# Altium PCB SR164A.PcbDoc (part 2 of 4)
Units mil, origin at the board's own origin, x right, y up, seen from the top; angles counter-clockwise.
Board outline 6100 x 4100 mil, 6 copper layers (Top Layer, Signal Layer 1, Signal Layer 2, Signal Layer 3, Signal Layer 4, Bottom Layer), stack 61.4 mil thick; 254 components, 116 nets, 656 pads, 2538 vias.
Unrouted connection lines stored in the file: 13.
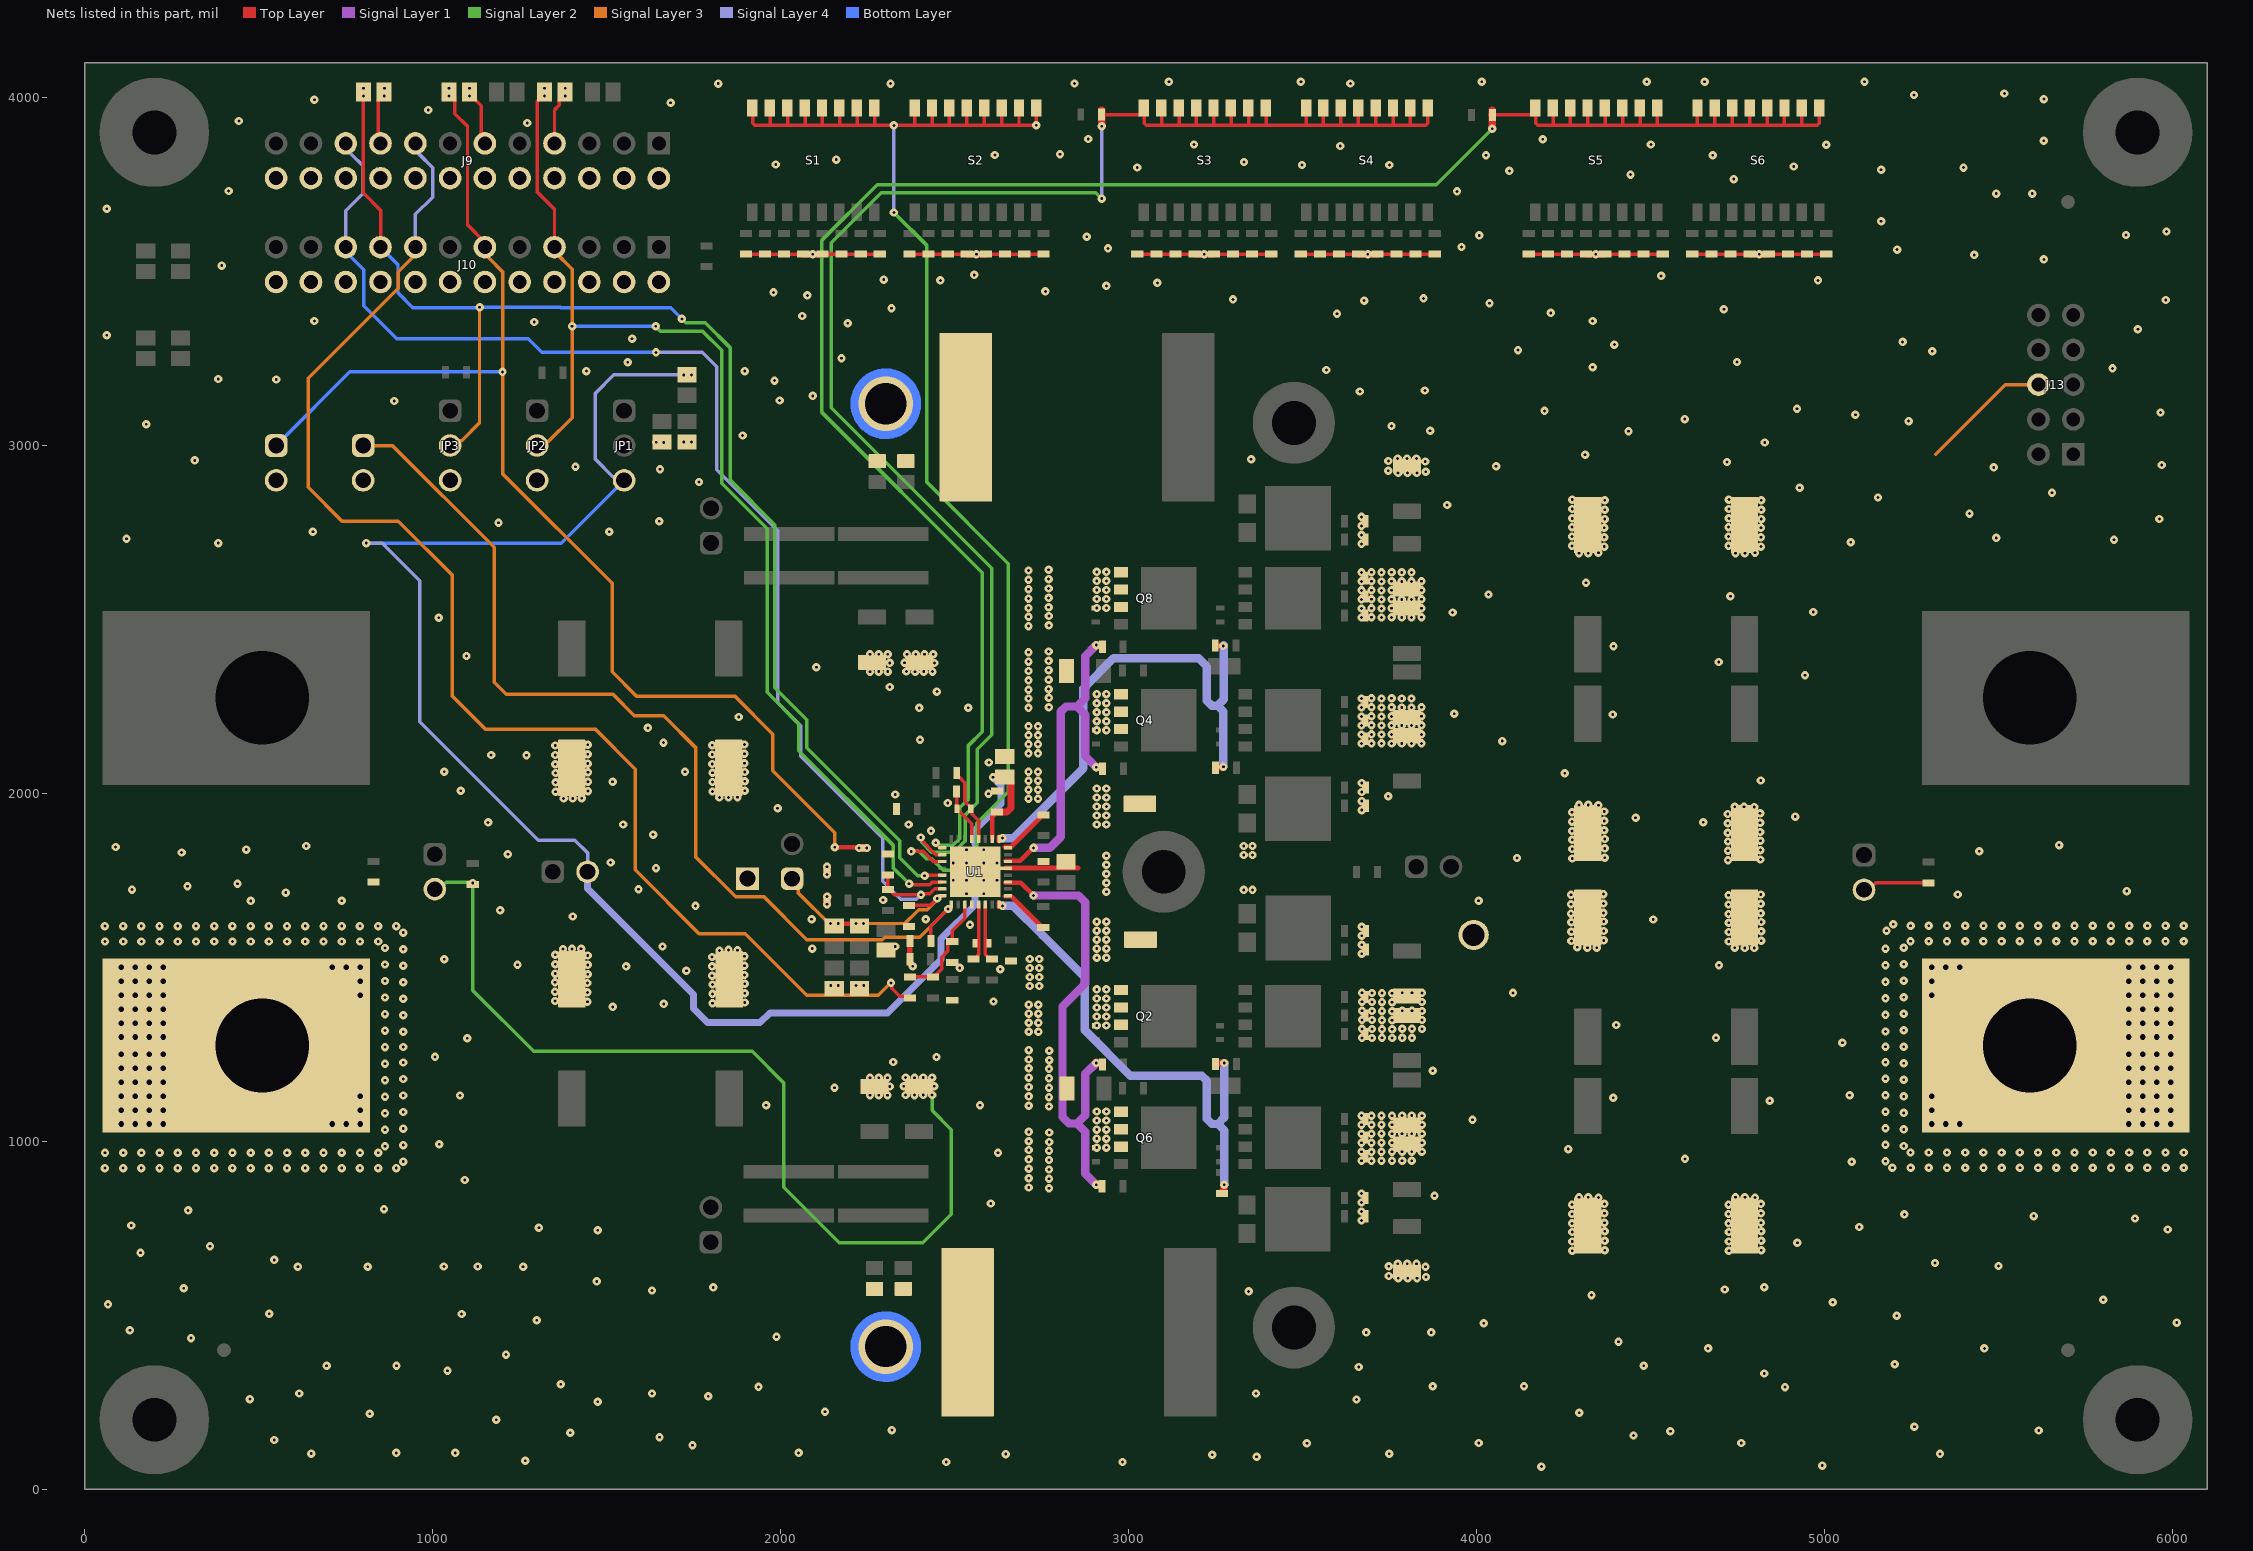
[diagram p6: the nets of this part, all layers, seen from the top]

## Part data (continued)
R47 R63 R79: library part CMP-0022509-4, "RES, 5.11 k, 1%, 0.1 W, AEC-Q200 Grade 0, 0603", Manufacturer=Vishay-Dale, Power_W=100mW, Supplier Part Number 1=541-5.11KHCT-ND, TempCo="100 ppm/C", Tolerance_%=1%, Value2=0.1W, Value_Code=5k11, ValueDisplayed=5.11k
R48 R64 R80: library part CMP-0022561-4, "RES, 6.49 k, 1%, 0.1 W, AEC-Q200 Grade 0, 0603", Manufacturer=Vishay-Dale, Power_W=100mW, Supplier Part Number 1=541-6.49KHCT-ND, TempCo="100 ppm/C", Tolerance_%=1%, Value2=0.1W, Value_Code=6k49, ValueDisplayed=6.49k
R49 R65 R81: library part CMP-0022635-4, "RES, 8.25 k, 1%, 0.1 W, AEC-Q200 Grade 0, 0603", Manufacturer=Vishay-Dale, Power_W=100mW, Supplier Part Number 1=541-8.25KHCT-ND, TempCo="100 ppm/C", Tolerance_%=1%, Value2=0.1W, Value_Code=8k25, ValueDisplayed=8.25k
R50 R66 R82: library part CMP-0022000-4, "RES, 10.5 k, 1%, 0.1 W, AEC-Q200 Grade 0, 0603", Manufacturer=Vishay-Dale, Power_W=100mW, Supplier Part Number 1=541-10.5KHCT-ND, TempCo="100 ppm/C", Tolerance_%=1%, Value2=0.1W, Value_Code=10k5, ValueDisplayed=10.5k
R51 R67 R83: library part CMP-0022043-4, "RES, 13.3 k, 1%, 0.1 W, AEC-Q200 Grade 0, 0603", Manufacturer=Vishay-Dale, Power_W=100mW, Supplier Part Number 1=541-13.3KHCT-ND, TempCo="100 ppm/C", Tolerance_%=1%, Value2=0.1W, Value_Code=13k3, ValueDisplayed=13.3k
R52 R68 R84: library part CMP-0022079-4, "RES, 16.2 k, 1%, 0.1 W, AEC-Q200 Grade 0, 0603", Manufacturer=Vishay-Dale, Power_W=100mW, Supplier Part Number 1=541-16.2KHCT-ND, TempCo="100 ppm/C", Tolerance_%=1%, Value2=0.1W, Value_Code=16k2, ValueDisplayed=16.2k
R53 R69 R85: library part CMP-0022205-4, "RES, 20.5 k, 1%, 0.1 W, AEC-Q200 Grade 0, 0603", Manufacturer=Vishay-Dale, Power_W=100mW, Supplier Part Number 1=541-20.5KHCT-ND, TempCo="100 ppm/C", Tolerance_%=1%, Value2=0.1W, Value_Code=20k5, ValueDisplayed=20.5k
R54 R70 R86: library part CMP-0022237-4, "RES, 24.9 k, 1%, 0.1 W, AEC-Q200 Grade 0, 0603", Manufacturer=Vishay-Dale, Power_W=100mW, Supplier Part Number 1=541-24.9KHCT-ND, TempCo="100 ppm/C", Tolerance_%=1%, Value2=0.1W, Value_Code=24k9, ValueDisplayed=24.9k
R55 R71 R87: library part CMP-0022324-4, "RES, 30.1 k, 1%, 0.1 W, AEC-Q200 Grade 0, 0603", Manufacturer=Vishay-Dale, Power_W=100mW, Supplier Part Number 1=541-30.1KHCT-ND, TempCo="100 ppm/C", Tolerance_%=1%, Value2=0.1W, Value_Code=30k1, ValueDisplayed=30.1k
R56 R72 R88: library part CMP-0022356-4, "RES, 36.5 k, 1%, 0.1 W, AEC-Q200 Grade 0, 0603", Manufacturer=Vishay-Dale, Power_W=100mW, Supplier Part Number 1=541-36.5KHCT-ND, TempCo="100 ppm/C", Tolerance_%=1%, Value2=0.1W, Value_Code=36k5, ValueDisplayed=36.5k
R89 R90 R103 R104: library part CMP-0022458-4, "RES, 4.99 k, 1%, 0.1 W, AEC-Q200 Grade 0, 0603", Manufacturer=Vishay-Dale, Power_W=100mW, Supplier Part Number 1=541-4.99KHCT-ND, TempCo="100 ppm/C", Tolerance_%=1%, Value2=0.1W, Value_Code=4k99, ValueDisplayed=4.99k
R91 R92 R96 R97 R98 R99 R100 R105 R106: library part CMP-0020442-3, "RES, 0, 5%, 0.125 W, AEC-Q200 Grade 0, 0805", Manufacturer=Vishay-Dale, Power_W=125mW, Supplier Part Number 1=541-0.0ACT-ND, TempCo="200 ppm/C", Tolerance_%=5%, Value2=0.125W, Value_Code=0000, ValueDisplayed=0
R93: library part CMP-0021246-3, "RES, 40.2 k, 1%, 0.125 W, AEC-Q200 Grade 0, 0805", Manufacturer=Vishay-Dale, Power_W=125mW, Supplier Part Number 1=541-40.2KCCT-ND, TempCo="100 ppm/C", Tolerance_%=1%, Value2=0.125W, Value_Code=40k2, ValueDisplayed=40.2k
R95: library part CMP-0025874-4, "RES, 0, 5%, 0.1 W, AEC-Q200 Grade 0, 0603", Manufacturer=Panasonic, Power_W=100mW, Supplier Part Number 1=P0.0GCT-ND, TempCo="600 ppm/C", Tolerance_%=5%, Value2=0.1W, Value_Code=0000, ValueDisplayed=0
R101 R102: library part CMP-0020842-3, "RES, 10.0 k, 1%, 0.125 W, AEC-Q200 Grade 0, 0805", Manufacturer=Vishay-Dale, Power_W=125mW, Supplier Part Number 1=541-10.0KCCT-ND, TempCo="100 ppm/C", Tolerance_%=1%, Value2=0.125W, Value_Code=10k0, ValueDisplayed=10.0k
S1 S2 S3 S4 S5 S6: library part CMP-0002229-1, "Switch, SPST, 8 Pos, 25mA, 24VDC, SMD", CurrentRating_mA=25A, Manufacturer="CTS Electrocomponents", Supplier Part Number 1=CT2188LPST-ND
SH-JP1 SH-JP2 SH-JP3 SH-JP4 SH-JP5 SH-JP6: library part CMP-0003642-1, "Shunt, 100mil, Flash Gold, Black", Manufacturer="Sullins Connector Solutions", Supplier Part Number 1=S9001-ND
T1 T2 T3 T4: library part CMP-0075010-2, "Terminal 70A Lug", Manufacturer=Panduit, Supplier Part Number 1=CXS70-14-C-ND
TP1 TP2 TP3 TP4: library part CMP-0067620-1, "PC Test Point, SMT", Manufacturer="TE Connectivity", Supplier Part Number 1=A106145CT-ND
TP5: library part CMP-0055143-2, "Test Point, Compact, Black, TH", Color=Black, Manufacturer="Keystone Electronics", Supplier Part Number 1=36-5006-ND
U1: library part CMP-0125346-2, "Wide-VIN, Dual-Phase, Automotive, Boost Controller With VOUT Tracking", Manufacturer="Texas Instruments", Max Supply Voltage=42V, Min Supply Voltage=2.5V, Operating Temperature Range="-40°C to +150°C", Output Voltage=6-60V, Switching Frequency=100-2200kHz
ZZ2: library part CMP-0077236-1
ZZ3: library part CMP-0077237-1
ZZ4: library part CMP-0077238-1
ZZ5 ZZ6 ZZ7 ZZ8 ZZ9 ZZ10: library part CMP-0077238-1, "These assemblies must comply with workmanship standards IPC-A-610 Class 2, unless otherwise specified."

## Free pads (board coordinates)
  round 236.22 hole 125.98: 2(3101,1775) 2(3475,465) 2(3475,3065)

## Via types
v1: diameter 24, hole 8, Top Layer to Bottom Layer, tented both sides, 2290 vias
v2: diameter 32, hole 16, Top Layer to Bottom Layer, 232 vias
v3: diameter 19.68, hole 7.87, Top Layer to Bottom Layer, tented both sides, 12 vias
v4: diameter 157.48, hole 118.11, Top Layer to Bottom Layer, tented both sides, 4 vias

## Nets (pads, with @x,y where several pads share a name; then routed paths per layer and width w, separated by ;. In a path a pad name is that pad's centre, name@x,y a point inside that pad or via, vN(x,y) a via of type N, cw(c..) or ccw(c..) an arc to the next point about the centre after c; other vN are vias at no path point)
AGND: C1.2 C2.1 C6.2 C7.2 C8.2 C15.2 C16.2 C17.2 C18.2 C19.2 C20.2 J7.2 J8.2 J9.2 J9.4 J9.6 J9.8 J9.10 J9.12 J9.14 J9.16 J9.18 J9.20 J9.22 J9.24 J10.2 J10.4 J10.6 J10.8 J10.10 J10.12 J10.14 J10.16 J10.18 J10.20 J10.22 J10.24 J13.6 J14.1 JP2.3 JP3.3 NT1.1 R5.1 R6.1 R7.1 R10.2 R41.2 R42.1 R43.2 R44.1 R45.2 R46.1 R47.1 R48.1 R49.1 R50.1 R51.1 R52.2 R53.1 R54.1 R55.1 R56.2 R57.2 R58.1 R59.2 R60.1 R61.2 R62.1 R63.1 R64.1 R65.1 R66.1 R67.1 R68.2 R69.1 R70.1 R71.1 R72.2 R73.2 R74.1 R75.2 R76.1 R77.2 R78.1 R79.1 R80.1 R81.1 R82.1 R83.1 R84.2 R85.1 R86.1 R87.1 R88.2 R91.1 R92.1 TP5.1 U1.4 U1.33 | length 2889
  Top Layer w10: C20.2@1635.96,3014.72 1646.48,3014.72 C20.2@1651.53,3009.67 ; R41.2@1900,3550 R42.1@1955,3550 R43.2@2010,3550 R44.1@2065,3550 ; R45.2@2120,3550 R46.1@2175,3550 R47.1@2230,3550 R48.1@2285,3550 ; R49.1@2370,3550 R50.1@2425,3550 R51.1@2480,3550 R52.2@2535,3550 ; C8.2@2371.16,1523.34 C8.2@2371.42,1523.6 ; C7.2@2371.42,1575.6 C7.2@2371.68,1575.86 ; R53.1@2590,3550 R54.1@2645,3550 R55.1@2700,3550 R56.2@2755,3550 ; R57.2@3025,3550 R58.1@3080,3550 R59.2@3135,3550 R60.1@3190,3550 ; R61.2@3245,3550 R62.1@3300,3550 R63.1@3355,3550 R64.1@3410,3550 ; R65.1@3495,3550 R66.1@3550,3550 R67.1@3605,3550 R68.2@3660,3550 ; R69.1@3715,3550 R70.1@3770,3550 R71.1@3825,3550 R72.2@3880,3550 ; R73.2@4150,3550 R74.1@4205,3550 R75.2@4260,3550 R76.1@4315,3550 ; R77.2@4370,3550 R78.1@4425,3550 R79.1@4480,3550 R80.1@4535,3550 ; R81.1@4620,3550 R82.1@4675,3550 R83.1@4730,3550 R84.2@4785,3550 ; R85.1@4840,3550 R86.1@4895,3550 R87.1@4950,3550 R88.2@5005,3550
  Top Layer w16: C8.2@2371.42,1523.6 C7.2@2371.42,1575.6
  Top Layer w19.5: R44.1@2065,3550 R45.2@2120,3550 ; R52.2@2535,3550 R53.1@2590,3550 ; R60.1@3190,3550 R61.2@3245,3550 ; R68.2@3660,3550 R69.1@3715,3550 ; R76.1@4315,3550 R77.2@4370,3550 ; R84.2@4785,3550 R85.1@4840,3550
  Top Layer w24: v1(1642.26,3009.19) C20.2@1664.06,3009.19 ; v1(1721.71,3010.08) R10.2@1743.51,3010.08 ; v1(2133.09,1767.29) C19.2@2133.09,1789.08 ; v1(2133.28,1681.63) C18.2@2133.28,1703.42 ; R92.1@2143.74,1442.26 R92.1@2165.53,1442.26 ; R91.1@2216.62,1442.26 R91.1@2238.41,1442.26
  Signal Layer 3 w10: 5320,2975 5520,3175 J13.6@5615,3175
  other v1: 4186.45,65.36 2475.91,78.74 2982.28,78.74 1266.1,81.95 3367.98,93.76 3748.98,102.35 895.32,104.67 4760.86,133.2 544.4,141.82 1651.67,149.42 4451.15,154.78 5258.39,180 1182.47,200 2127.4,222.78 1474.34,251.82 1791.88,267.68 616.14,275.59 3365.99,275.61 4886.58,293.85 4136.54,296.13 3661.65,351.69 895.67,355.06 4480.32,355.37 1210.63,387.3 305.12,434.65 1988.19,438.5 3869.81,451.15 129.68,457.09 6012.25,479.15 5208.03,499.02 529.9,504.41 4330.32,558.3 4713.32,574.26 1806.55,580.38 1471.4,597.62 1259.84,639.76 1031.98,640.62 5500.11,641.89 544.4,659.45 159.9,679.66 4922.23,708.9 5892.59,778.3 5229.67,790.26 296.86,801.8 859.84,805.43 3879.13,843.8 5078.44,941.3 1018.59,991.53 1958.21,1104.11 2573.06,1104.11 4842.86,1116.8 4393.2,1125.38 2154.58,1154.14 3874.24,1203.33 2323.29,1228.37 2448.08,1242.42 5051.46,1283.26 1098.92,1296.48 1517.58,1386.6 2611.67,1402.11 4104.99,1426.88 2143.74,1448.16 2165.7,1447.99 2216.62,1448.16 2238.58,1447.99 1729.06,1490.35 2630.99,1494.8 2514.73,1498.7 2379.78,1503.66 4696.64,1505.96 1243.43,1507.46 1032.9,1523.32 2090.75,1554.17 1660.51,1560 2329.61,1560.1 2544.08,1622.37 2088.91,1638.62 2416.76,1638.62 1755.3,1676.79 476.79,1691.26 2294.36,1693.93 2133.45,1703.59 5868.52,1719.34 135.59,1723.67 1591.34,1725 295.19,1733.52 2133.25,1789.25 1511.32,1801.79 4116.39,1814.44 1216.11,1825 464.1,1838.54 88.58,1846 636.21,1848.83 5674.44,1851.54 1633.34,1881.65 2432.24,1892.38 1547.19,1910.73 2367.74,1910.73 1159.12,1916.88 4457.26,1930.36 1991.29,1957.38 2480.18,1972.71 3746.27,1992.04 2329.59,1997.1 2597.23,1999.24 4817.01,2037.4 1032.9,2062.28 1725.03,2062.28 2598.54,2089.08 1269.35,2110.12 4073.61,2150.42 2400.55,2154.37 1618.38,2188.38 1879.57,2219.71 4391.5,2227.08 3935.85,2229.03 2539.3,2246.05 2449.02,2292.72 2313.73,2305.79 4943.91,2340 2102.77,2362.94 1097.22,2395.24 1017.3,2505.09 3931.27,2520.26 4729.64,2566.76 4314.5,2605.44 383.49,2719.54 5075.71,2722.3 5832.3,2729.02 119.73,2732 655.59,2751.99 1651.03,2782.43 5416.82,2804.32 3915.4,2828.93 1653.2,2931.91 1410.41,2939.01 5969.45,2944.16 316.11,2957.29 4311.97,2973.74 1664.22,3009.03 4828.3,3008.7 1743.67,3009.91 1890.63,3028.67 3866.49,3042.32 176.53,3060.84 4598.16,3075.85 5088.82,3088.3 889.59,3127.82 2092.5,3142.71 3664.79,3155.26 1982.08,3186.63 550,3189.56 383.49,3191.15 1441.62,3213.93 1896.93,3213.93 1560.43,3239.5 2174.67,3250.7 4396.27,3290.09 5224.54,3297.79 1573.09,3307.09 62.95,3316.93 5900.88,3334.1 2193,3351.42 1291.78,3355.15 659.93,3357.93 3598.91,3378.47 4213.39,3381.16 4710.9,3391.92 3847.66,3422.84 2076.77,3431.44 2936.25,3458.82 2458.99,3474.68 393.7,3517.18 5430.27,3547.89 2092.5,3550 2562.5,3550 3217.5,3550 3687.5,3550 4342.5,3550 4812.5,3550 2879.54,3600.33 4007.65,3603.97 5982.9,3615.12 5162.69,3644.7 62.95,3680.5 5597,3724.03 3944.05,3730.31 413.39,3731.41 4739.14,3765.72 4442.47,3778.63 3025,3799.21 5399.5,3798.74 1985.87,3807.67 3331.78,3814.85 4027.05,3834.1 2615.69,3834.79 3608.07,3861.07 5005,3864.15 4190.54,3880.01 2883.86,3880.89 1271.79,3926.76 442.91,3932.74 987.11,3964.36 1683.75,3985.27 659.93,3994.06 5630.61,3995.64 3637.39,4040.57 3115.77,4045.28 4655.51,4045.28 5115.17,4045.28
  other v3: 2534.2,1712.01 2583.8,1712.01 2496.01,1750.2 2534.2,1750.2 2583.8,1750.2 2621.99,1750.2 2496.01,1799.8 2534.2,1799.8 2583.8,1799.8 2621.99,1799.8 2534.2,1837.99 2583.8,1837.99
ATRK/DTRK: C17.1 JP5.1 R93.2 R94.2 U1.32 | length 698.8
  Top Layer w10: C17.1@2369.19,1672.83 C17.1@2369.19,1678.24 ; C17.1@2385.28,1678.24 2430.1,1678.24 v1(2449.92,1698.07) v1@2449.92,1698.25 ; U1.32@2457.78,1706.1 U1.32@2464.51,1706.1
  Top Layer w12: R94.2@2165.17,1625.32 R93.2@2216.69,1625.32
  Top Layer w16: v1@2449.81,1697.29 U1.32@2455.47,1702.94
  Top Layer w24: v1(2143.57,1626.39) R94.2@2165.36,1626.39 ; v1(2216.45,1626.39) R93.2@2238.25,1626.39
  Signal Layer 3 w10: JP5.1@2032.92,1754.76 2049.95,1737.73 2049.95,1715.14 v1@2143.74,1621.35 ; v1@2150.52,1623.86 v1@2165.53,1623.86 ; v1(2165.53,1626.23) v1@2216.29,1626.23 ; v1@2216.62,1621.79 2217.14,1621.27 2238.06,1621.27 v1@2238.58,1621.79 ; v1(2238.41,1626.23) 2356.44,1626.23 2392.15,1661.94 2396.31,1666.1 2421.06,1666.1 2449.92,1694.97 v1(2449.92,1698.07)
ATRK_EXT: J8.1 J10.11 R99.1 R104.2 | length 3640.4
  Top Layer w10: R99.1@1046.87,4015.75 1063.52,3999.09 1063.52,3953.49 1099.92,3917.09 1099.92,3633.99 1150,3583.91 J10.11@1150,3570
  Top Layer w12: v1(2155.21,1845.18) R104.2@2244.29,1845.18 ; R104.2@2234.6,1845.18 R104.2@2236.35,1843.43
  Top Layer w24: v1(2225.46,1843.43) R104.2@2247.25,1843.43
  Signal Layer 3 w10: J10.11@1160.52,3559.48 1160.52,3539.78 1200.6,3499.7 v1(1200.6,3211.56) 1200.6,2919.05 1515.62,2604.03 1515.62,2349.38 1585,2280 1867.8,2280 1977.16,2170.64 1977.16,2065.07 2155.21,1887.02 v1(2155.21,1845.18)
  Signal Layer 4 w10: J10.11@1150,3570 J10.11@1160.52,3559.48
  Bottom Layer w10: J8.1@551.18,3012.89 562.89,3012.89 761.56,3211.56 v1(1200.6,3211.56)
  other v1: 2247.42,1843.26 1046.7,4004.68 1046.87,4026.64
ATRK_EXT_SEC: J9.11 R99.2 | length 165.7
  Top Layer w10: R99.2@1105.92,4015.75 1105.92,4009.84 1139.01,3976.76 1139.01,3901.65 1139.48,3901.18 1139.48,3878.83 J9.11@1150,3868.31
  other v1: 1105.76,4004.68 1105.92,4026.64
BIAS: C1.1 C2.2 JP1.3 JP4.2 R9.1 U1.18 | length 4888.6
  Top Layer w10: C2.2@2644.11,2046.9 C2.2@2644.25,2046.77
  Top Layer w13: U1.18@2608.21,1869.49 2608.21,1932.5 C1.1@2615.83,1940.11
  Top Layer w20: C1.1@2621.99,1947.06 2650.14,1947.06 2661.85,1958.78 2661.85,2035.07 2650.15,2046.77 C2.2@2644.25,2046.77
  Top Layer w22: v1@2611.01,2046.9 C2.2@2644.11,2046.9
  Top Layer w24: v1(1721.71,3202.98) R9.1@1743.51,3202.98
  Signal Layer 4 w10: v1(808.96,2719.54) 854.5,2719.54 963.13,2610.91 963.13,2206.35 1303.6,1865.88 1408.15,1865.88 1445,1829.03 JP4.2@1445,1775 ; JP1.3@1539.48,2910.52 1517.85,2910.52 1467.76,2960.61 1467.76,3150.57 1520.16,3202.98 v1(1721.71,3202.98)
  Signal Layer 4 w14: 2559,1698.29 2559,1858.29
  Signal Layer 4 w20: JP4.2@1445,1775 1445,1726.52 1749.93,1421.59 1749.93,1381.6 1790.27,1341.26 1941.2,1341.26 1969.19,1369.25 2307.32,1369.25 2461.28,1523.21 2461.28,1582.45 2558.83,1680.01 2558.83,1699.23 ; 2558.33,1855.19 2558.33,1894.93 2633.28,1969.88 2633.28,2001.6 2633.28,2023.56 v1(2610.25,2046.6)
  Bottom Layer w10: v1(808.96,2719.54) 1369.54,2719.54 JP1.3@1550,2900 JP1.3@1539.48,2910.52
  other v1: 1743.67,3202.81
CFG0: S1.9 S1.10 S1.11 S1.12 S1.13 S1.14 S1.15 S1.16 S2.9 S2.10 S2.11 S2.12 S2.13 S2.14 S2.15 S2.16 U1.27 | length 4212.1
  Top Layer w10: S1.16@1920,3970 1920,3925.86 1925.86,3920 1970,3920 ; S1.15@1970,3970 1970,3920 ; S1.14@2020,3970 2020,3920 ; 2070,3921 S1.13@2070,3970.79 ; 2120,3920 2020,3920 ; 2120,3920.79 S1.12@2120,3970.79 ; 2121,3920 2169,3920 ; S1.11@2170,3970.79 2170,3920 v1(2325.46,3920) 2729.14,3920 2735,3925.86 S2.9@2735,3970 ; 2220,3921 S1.10@2220,3970.79 ; 2270,3920.79 S1.9@2270,3970.79 ; v1@2377.23,1833.44 2377.38,1833.59 2409.89,1833.59 2439.1,1804.39 2455.75,1804.39 2455.81,1804.45 U1.27@2457.7,1804.45 ; 2385,3920.79 S2.16@2385,3970 S2.16@2385,3970.79 ; 2435,3920.79 S2.15@2435,3970 S2.15@2435,3970.79 ; 2485,3921.79 S2.14@2485,3970 S2.14@2485,3971.57 ; 2535,3921.57 S2.13@2535,3970 S2.13@2535,3971.57 ; 2585,3920.79 S2.12@2585,3970 S2.12@2585,3971.57 ; 2635,3921.79 S2.11@2635,3970 S2.11@2635,3971.57 ; 2685,3921.57 S2.10@2685,3970 S2.10@2685,3971.57 ; 1970,3920 2020,3920
  Signal Layer 2 w10: v1(2325.46,3669.74) 2420.46,3574.74 2420.46,2894.45 2654.44,2660.47 2654.44,2004.84 2562.96,1913.36 2562.96,1797.42 2544.5,1778.96 2467.19,1778.96 2433.64,1812.51 2418.29,1812.51 2397.21,1833.59 2392.15,1833.59 v1@2377.38,1833.59
  Signal Layer 4 w10: v1(2325.46,3669.74) v1(2325.46,3920)
  other v1: 2375.4,1833.44 2734.46,3920.25
CFG1: R39.2 S3.9 S3.10 S3.11 S3.12 S3.13 S3.14 S3.15 S3.16 S4.9 S4.10 S4.11 S4.12 S4.13 S4.14 S4.15 S4.16 U1.26 | length 4996
  Top Layer w10: v1@2403.61,1866.64 2446.04,1824.21 U1.26@2457.7,1824.21 ; R39.2@2928,3950.31 S3.16@3043.9,3950.31 ; S3.16@3045,3970 3045,3925.86 3050.86,3920 3245,3920 3854.14,3920 3860,3925.86 S4.9@3860,3970 ; 3095,3920.79 S3.15@3095,3970.79 ; 3145,3920.79 S3.14@3145,3970.79 ; 3195,3921.79 S3.13@3195,3971.57 ; 3245,3921.57 S3.12@3245,3971.57 ; 3295,3920.79 S3.11@3295,3971.57 ; 3345,3921.79 S3.10@3345,3971.57 ; 3395,3921.57 S3.9@3395,3971.57 ; 3510,3920.79 S4.16@3510,3970 S4.16@3510,3970.79 ; 3560,3920.79 S4.15@3560,3970 S4.15@3560,3970.79 ; 3610,3921.79 S4.14@3610,3970 S4.14@3610,3971.57 ; 3660,3921.57 S4.13@3660,3970 S4.13@3660,3971.57 ; 3710,3920.79 S4.12@3710,3970 S4.12@3710,3971.57 ; 3760,3921.79 S4.11@3760,3970 S4.11@3760,3971.57 ; 3810,3921.57 S4.10@3810,3970 S4.10@3810,3971.57
  Top Layer w22: R39.2@2922.44,3951.1 2922.62,3950.93 2922.62,3917.56 v1(2922.79,3917.39) ; R39.2@2922.62,3951.28 R39.2@2922.62,3963.43
  Signal Layer 2 w10: v1@2404.27,1869.49 2405.37,1868.39 2405.37,1859.3 2432.99,1831.67 2498.4,1831.67 2530.27,1863.54 2530.27,1938.03 2565.01,1972.76 2565.01,2001.6 2565.01,2127.28 2606.9,2169.17 2606.9,2647.66 2145.67,3108.89 2145.67,3582.77 2289.38,3726.48 2905.97,3726.48 v1(2922.79,3709.66)
  Signal Layer 4 w10: v1(2922.79,3709.66) v1(2922.79,3917.39)
  other v1: 2402.69,1873.39
CFG2: R40.2 S5.9 S5.10 S5.11 S5.12 S5.13 S5.14 S5.15 S5.16 S6.9 S6.10 S6.11 S6.12 S6.13 S6.14 S6.15 S6.16 U1.25 | length 5889.6
  Top Layer w10: v1@2446.44,1859.14 2449.12,1856.46 2449.12,1852.55 2457.78,1843.9 U1.25@2464.51,1843.9 ; R40.2@4045.28,3950.31 S5.16@4168.9,3950.31 ; S5.16@4170,3970 4170,3950.31 4170,3925.86 4175.86,3920 4220,3920 4270,3920 4320,3920 4370,3920 4420,3920 4470,3920 4520,3920 4577.5,3920 4635,3920 4685,3920 4735,3920 4785,3920 4835,3920 4885,3920 4935,3920 4979.14,3920 4985,3925.86 S6.9@4985,3970 ; 4220,3920.79 S5.15@4220,3970.79 ; 4270,3920.79 S5.14@4270,3970.79 ; 4320,3921.79 S5.13@4320,3971.57 ; 4370,3921.57 S5.12@4370,3971.57 ; 4420,3920.79 S5.11@4420,3971.57 ; 4470,3921.79 S5.10@4470,3971.57 ; 4520,3921.57 S5.9@4520,3971.57 ; 4635,3920.79 S6.16@4635,3970 S6.16@4635,3970.79 ; 4685,3920.79 S6.15@4685,3970 S6.15@4685,3970.79 ; 4735,3921.79 S6.14@4735,3970 S6.14@4735,3971.57 ; 4785,3921.57 S6.13@4785,3970 S6.13@4785,3971.57 ; 4835,3920.79 S6.12@4835,3970 S6.12@4835,3971.57 ; 4885,3921.79 S6.11@4885,3970 S6.11@4885,3971.57 ; 4935,3921.57 S6.10@4935,3970 S6.10@4935,3971.57
  Top Layer w22: R40.2@4044.61,3950.31 4044.89,3950.03 v1(4044.89,3910.3) ; R40.2@4045.28,3950.31 R40.2@4045.3,3963.38
  Signal Layer 2 w10: v1@2446.44,1859.14 2448.49,1859.14 2456.86,1850.77 2494.87,1850.77 2514.27,1870.17 2514.27,1958.72 2539.72,1984.17 2539.72,2001.6 2539.72,2137.97 2579.47,2177.71 2579.47,2634.4 2117.41,3096.46 2117.41,3589.24 2278,3749.83 3884.42,3749.83 v1(4044.89,3910.3)
  other v1: 2445.47,1858.37
COMP: J9.15 J10.15 R95.1 | length 3912.3
  Top Layer w10: v1@2316.48,1463.18 2319.16,1460.5 2319.16,1439.94 2341.69,1417.4 2366.77,1417.4 R95.1@2371.77,1412.4
  Signal Layer 3 w10: J10.15@939.48,3559.48 939.48,3537.85 900.65,3499.02 900.65,3452.33 641.98,3193.66 641.98,2879.78 739.32,2782.43 901.15,2782.43 1056.75,2626.83 1056.75,2279.12 1151.9,2183.97 1468.01,2183.97 1581.98,2070 1581.98,1780.35 1765.35,1596.98 1897.91,1596.98 2074.5,1420.4 2280.95,1420.4 v1@2316.12,1455.57
  Signal Layer 4 w10: J10.15@939.48,3559.48 J10.15@950,3570 950,3664.15 999.85,3714 999.85,3798.52 960.52,3837.86 960.52,3857.79 J9.15@950,3868.31
  other v1: 2317.23,1455.54
CSN1: C11.2 R16.1 U1.5 | length 172.1
  Top Layer w10: R16.1@2554.63,1524.14 2568.84,1538.35 2568.84,1592.6 U1.5@2568.84,1680.51 ; C11.2@2558.41,1569.32 2568.3,1569.32
CSN2: C12.1 R18.1 U1.21 | length 154.2
  Top Layer w10: R18.1@2505.92,2005.78 2505.92,2001.6 2505.92,1955.83 2549.16,1912.59 U1.21@2549.16,1869.49
CSP1: C11.1 R15.1 U1.6 | length 182.4
  Top Layer w10: U1.6@2588.53,1680.51 2588.53,1592.6 2588.53,1569.32 ; C11.1@2595.91,1576.32 C11.1@2598.41,1573.82 ; C11.1@2598.41,1569.32 2588.53,1569.32 ; R15.1@2607.39,1522.98 2601.26,1522.98 2595.1,1529.14 2595.1,1530.56 2588.53,1537.13 2588.53,1569.32
CSP2: C12.2 R17.1 U1.20 | length 217.8
  Top Layer w10: R17.1@2506.08,2059.06 2506.08,2051.56 2511.08,2046.56 2513.88,2046.56 2529.47,2030.97 2529.47,2001.6 2529.47,1977.18 2543.14,1963.52 2544.08,1963.52 2546.58,1961.02 C12.2@2546.58,1956.52 2549.08,1954.02 2549.08,1941.17 2568.87,1921.38 U1.20@2568.87,1869.52
DLY: C7.1 J7.1 U1.1 | length 2840.8
  Top Layer w10: C7.1@2431.68,1575.86 2431.68,1592.6 2431.68,1618.55 v1(2481.22,1668.09) 2484.41,1668.09 U1.1@2490.02,1673.7
  Signal Layer 3 w10: J7.1@800,3000 883.79,3000 1176.72,2707.08 1176.72,2319.36 1211.08,2285 1518.14,2285 1579.63,2223.51 1664.03,2223.51 1755.3,2132.24 1755.3,1818.43 1870.56,1703.17 1952.14,1703.17 2075.37,1579.93 2292.42,1579.93 2299.43,1586.94 2400.07,1586.94 2405.73,1592.6 v1(2481.22,1668.09)
EN2: J10.7 JP2.2 R97.1 U1.30 | length 3463.1
  Top Layer w10: v1(1320.96,4004.73) 1316.11,4004.73 1299.74,3988.37 1299.74,3728.98 1350,3678.73 J10.7@1350,3570 ; v1(2369.19,1740.55) 2371.77,1737.97 2428.93,1737.97 2436.35,1745.39 2464.43,1745.39 U1.30@2464.51,1745.47
  Top Layer w24: R97.1@1321.13,4004.9 v1(1321.13,4026.69)
  Signal Layer 2 w10: v1(1640.82,3342.69) 1654.44,3329.06 1774.65,3329.06 1830.35,3273.36 1830.35,2891.75 1960.92,2761.18 1960.92,2291.33 2052.52,2199.74 2052.52,2122.22 2322.98,1851.76 2322.98,1786.76 v1(2369.19,1740.55)
  Signal Layer 3 w10: JP2.2@1305.84,3002.28 1314.07,3010.52 1331.22,3010.52 1400.53,3079.83 v1(1400.53,3342.69) 1400.95,3343.11 1400.95,3506.6 1350,3557.55 J10.7@1350,3570
  Bottom Layer w10: v1(1400.53,3342.69) v1(1640.82,3342.69)
  Bottom Layer w24: v1@1321.13,4004.9 v1(1321.13,4026.69)
EN2_SEC: J9.7 R97.2 | length 195.9
  Top Layer w10: J9.7@1350,3868.31 1350,3964.36 1364.13,3978.49 1364.13,3993.19 1375.67,4004.73 v1(1380.96,4004.73)
  Top Layer w24: R97.2@1381.13,4004.9 v1(1381.13,4026.69)
  Bottom Layer w24: v1@1381.13,4004.9 v1(1381.13,4026.69)
GND: C3.2 C4.2 C21.1 C22.1 C23.1 C24.1 C25.1 C26.1 C27.1 C28.1 C29.2 C30.2 C31.1 C32.1 C33.1 C34.1 C35.1 C36.1 C37.1 C38.1 C39.1 C40.1 C41.2 C42.2 C43.2 C44.2 C45.2 C46.2 C47.2 C48.2 C49.2 C50.2 C51.2 C52.2 C53.2 C54.2 C55.2 C56.2 C57.2 C58.2 C59.2 C60.2 C61.1 C62.1 C63.1 C64.1 C65.1 C66.1 C67.1 C68.1 C69.2 J2.1 J4.1 J5.2 J6.2 NT1.2 Q2.1 Q2.2 Q2.3 Q4.1 Q4.2 Q4.3 Q6.1 Q6.2 Q6.3 Q8.1 Q8.2 Q8.3 R29.1 R30.1 R32.1 R34.1 R36.1 R38.1 T2.1 T4.1 TP3.1 TP4.1 U1.13 | length 3126.2
  Top Layer w10: J6.2@5113.01,1726.89 5128.44,1726.89 5132.18,1726.89 5128.44,1723.15 J6.2@5113.57,1723.15 5127.21,1723.15 5131.56,1727.5 5146.9,1742.85 C69.2@5299.21,1742.85
  Top Layer w13.5: U1.13@2646.2,1785.95 2685.2,1785.95
  Top Layer w15: 2683.79,1785.88 2819.75,1785.88 2853.79,1785.88
  Signal Layer 2 w10: J5.2@1020.27,1727 1021.11,1727 1039.32,1745.2 1115.22,1745.2 1115.22,1433.76 1290.33,1258.65 1918.12,1258.65 2008.86,1167.9 2008.86,868.03 2168.51,708.38 2408.24,708.38 2490.81,790.96 2490.81,1033.28 2435.2,1088.9 v1(2435.2,1133.31)
  Signal Layer 4 w10: J5.2@991.18,1715.06 1004.45,1715.06 J5.2@1004.45,1717.06 ; v1@2409.71,1139.47 v1@2412.23,1136.94
  other v1: 4993.69,68.11 3240.45,99.46 2647.07,101.17 5332.12,101.91 650.99,102.65 1064.69,104.67 2051.49,104.67 1746.77,126.87 3512.33,132.35 4006.14,133.2 1395.15,162.75 4557.22,166.89 5616.08,169.29 2319.63,170.14 818.97,217.47 4294.91,219.83 3654.79,258.33 474.55,259.32 1630.13,275.59 1936.47,294.36 3874.27,296.13 1368.11,301.97 4826.76,332.93 1042.49,340.78 694.95,355.06 5202.17,359.4 4665.51,405.13 5459.66,405.13 4408.02,424.38 3682.79,451.15 4020.58,477.32 1298.77,486.07 1082.92,503.95 66.84,531.5 5024.09,537.48 5801.38,544.7 3345,568.98 1630.13,571.55 284.63,577.99 4826.74,580.8 3775.04,606.78 3802.04,606.78 3829.04,606.78 3854.76,610.46 3747.88,613.27 612.5,639.76 813.52,639.76 3853.29,639.73 1129.4,640.62 3747.88,640.9 3773.59,648.14 3800.59,648.14 3827.59,648.14 5317.68,650.59 4275.29,685.41 4725.25,685.41 4368.33,687.45 4818.29,687.45 359.87,698.82 4275.29,712.41 4725.25,712.41 4368.33,714.45 4818.29,714.45 4275.29,739.41 4725.25,739.41 4368.33,741.45 4818.29,741.45 1474.34,744.38 5986.68,746.85 1305.02,751.81 5099.81,754.07 133.34,758.25 4274.33,764.41 4724.29,764.41 4367.37,766.45 4817.33,766.45 3669.26,772.48 5601.64,785.35 4274.33,791.41 4724.29,791.41 4367.37,793.45 4817.33,793.45 3669.26,798.41 4274.33,818.41 4724.29,818.41 4367.37,820.45 4817.33,820.45 2604.04,821.51 3669.26,824.34 4350.33,838.37 4800.29,838.37 4294.33,839.37 4321.33,839.37 4744.29,839.37 4771.29,839.37 3669.26,850.26 2771.13,865.36 2713.22,867.36 1092.23,888.92 2771.13,892.36 2713.22,894.36 2771.13,919.36 2713.22,921.36 57.72,923.14 110.07,923.14 162.42,923.14 214.77,923.14 267.12,923.14 319.47,923.14 371.82,923.14 424.17,923.14 476.52,923.14 528.87,923.14 581.22,923.14 633.57,923.14 685.92,923.14 738.27,923.14 790.62,923.14 842.97,923.14 895.32,923.14 5195.28,924.06 5247.63,924.06 5299.98,924.06 5352.33,924.06 5404.68,924.06 5457.03,924.06 5509.38,924.06 5561.73,924.06 5614.08,924.06 5666.43,924.06 5718.78,924.06 5771.13,924.06 5823.48,924.06 5875.83,924.06 5928.18,924.06 5980.53,924.06 6032.88,924.06 915,941.86 5175.6,942.78 3669.26,944.43 3698.14,944 3756.91,944.14 3727.02,944.57 3786.09,944.51 3814,944.51 2771.13,946.36 2713.22,948.36 4599.06,949.76 57.99,967.3 110.34,967.3 162.69,967.3 215.04,967.3 267.39,967.3 319.74,967.3 372.09,967.3 424.44,967.3 476.79,967.3 529.14,967.3 581.49,967.3 633.84,967.3 686.19,967.3 738.54,967.3 790.89,967.3 843.24,967.3 2624.77,967.07 5247.36,968.23 5299.71,968.23 5352.06,968.23 5404.41,968.23 5456.76,968.23 5509.11,968.23 5561.46,968.23 5613.81,968.23 5666.16,968.23 5718.51,968.23 5770.86,968.23 5823.21,968.23 5875.56,968.23 5927.91,968.23 5980.26,968.23 6032.61,968.23 3669.26,970.36 3698.14,969.93 3727.02,970.5 3756.91,970.07 3786.09,970.44 3814,970.44 3842.89,970.01 2771.13,973.36 2713.22,975.36 4263.33,977.77 2908.75,982.08 2936.25,982.08 862.92,986.02 5227.68,986.95 915,989.34 5175.6,990.27 3669.26,996.28 3698.14,995.85 3727.02,996.42 3756.91,995.99 3842.89,995.93 2772.09,998.36 2713.22,1000.36 2908.75,1008.01 2936.25,1008.01 3669.26,1022.21 3698.14,1021.78 3727.02,1022.35 3756.91,1021.92 3786.09,1022.29 3814,1022.29 3842.89,1021.86 2772.09,1025.36 2713.22,1027.36 862.92,1033.51 2908.75,1033.93 2936.25,1033.93 5227.68,1034.43 915,1036.83 5175.6,1037.75 3669.26,1048.14 3698.14,1047.71 3727.02,1048.28 3756.91,1047.85 3842.89,1047.78 2908.75,1059.86 2936.25,1059.86 3988.27,1062.09 3669.26,1074.06 3698.14,1073.63 3727.02,1074.2 3756.91,1073.77 3786.09,1074.14 3814,1074.14 3842.89,1073.71 862.92,1080.99 5227.68,1081.92 915,1084.31 5175.6,1085.24 2908.75,1085.79 2936.25,1085.79 2771.13,1100.36 2713.22,1102.36 2771.13,1127.36 862.92,1128.48 2713.22,1129.36 5227.68,1129.4 915,1131.8 1078.2,1131.8 2256.55,1132.6 2281.61,1132.9 2307.1,1132.78 2359.16,1133.47 2384.65,1133.13 2409.71,1133.43 5072.19,1132.72 5175.6,1132.72 2771.13,1154.36 2713.22,1156.36 2313.3,1157.83 2441.4,1158.37 2353.48,1158.54 862.92,1175.96 5227.68,1176.89 915,1179.28 5175.6,1180.21 2771.13,1181.36 2256.55,1182.68 2281.61,1182.98 2307.1,1182.85 2384.65,1183.21 2435.2,1183.39 2713.22,1183.36 2359.16,1183.54 2409.71,1183.51 2771.13,1208.36 2713.22,1210.36 862.92,1223.44 5227.68,1224.37 915,1226.77 5175.6,1227.69 2772.09,1233.36 2713.22,1235.36 1006.63,1242.78 2772.09,1260.36 2713.22,1262.36 862.92,1270.93 915.22,1271.39 5175.6,1271.85 5227.68,1271.85 3670.62,1297.45 3699.51,1297.02 3757.28,1297.16 3728.39,1297.59 3786.46,1297.53 3814.37,1297.53 4688.06,1297.59 915,1315.09 2713.22,1315.33 2740.72,1315.33 5175.6,1316.02 862.92,1318.41 5227.68,1319.34 3757.28,1322.09 3670.62,1323.38 3699.51,1322.95 3728.39,1322.52 3786.46,1323.45 3814.37,1323.45 3843.26,1323.02 2908.75,1333.08 2936.25,1333.08 4401.78,1334.73 2713.22,1341.26 2740.72,1341.26 3728.39,1348.44 3757.28,1348.01 3670.62,1349.3 3699.51,1348.87 3843.26,1348.95 2908.75,1359.01 2936.25,1359.01 915,1362.58 5175.6,1363.5 862.92,1365.9 2713.22,1367.19 2740.72,1367.19 5227.68,1366.82 3728.39,1374.37 3757.28,1373.94 3670.62,1375.23 3699.51,1374.8 3786.46,1375.31 3814.37,1375.31 3843.26,1374.88 2908.75,1384.93 2936.25,1384.93 2713.22,1393.11 2740.72,1393.11 1664.21,1395.18 1803.89,1397.02 1896.93,1399.06 3728.39,1400.29 3757.28,1399.86 1444.5,1401.26 3670.62,1401.15 3699.51,1400.72 3843.26,1400.8 1351.46,1403.3 915,1410.06 2908.75,1410.86 2936.25,1410.86 5175.6,1410.99 862.92,1413.38 5227.68,1414.31 1803.89,1424.02 1896.93,1426.06 3728.39,1426.22 3757.28,1425.79 3670.62,1427.08 3699.51,1426.65 3786.46,1427.16 3814.37,1427.16 3843.26,1426.73 1444.5,1428.26 1351.46,1430.3 2908.75,1436.79 2936.25,1436.79 2715.91,1446.59 2743.41,1446.59 1803.89,1451.02 1896.93,1453.06 1444.5,1455.26 1351.46,1457.3 915,1457.55 5175.6,1458.47 862.92,1460.87 5227.68,1461.79 2715.91,1472.51 2743.41,1472.51 1802.93,1476.02 1895.97,1478.06 1445.46,1480.26 1352.42,1482.3 2715.91,1498.44 2743.41,1498.44 1555.77,1503.02 1802.93,1503.02 915,1505.03 1895.97,1505.06 5175.6,1505.96 1445.46,1507.26 862.92,1508.35 1352.42,1509.3 5227.68,1509.28 2715.91,1524.37 2743.41,1524.37 2908.71,1528.08 2936.21,1528.08 1802.93,1530.02 1895.97,1532.06 1445.46,1534.26 1352.42,1536.3 3669.87,1539.34 1824.06,1548.64 1850.02,1550.44 1876.06,1549.6 915,1552.52 1374.52,1552.95 1400.41,1553.24 5175.6,1553.44 1426.52,1553.91 2908.71,1554 2936.21,1554 862.92,1555.84 4770.99,1555.79 4797.99,1555.79 4318.67,1556.84 4345.67,1556.84 4741.99,1556.79 5227.68,1556.76 4289.67,1557.84 3669.87,1565.27 57.99,1574.56 110.34,1574.56 162.69,1574.56 215.04,1574.56 267.39,1574.56 319.74,1574.56 372.09,1574.56 424.44,1574.56 476.79,1574.56 529.14,1574.56 581.49,1574.56 633.84,1574.56 686.19,1574.56 738.54,1574.56 790.89,1574.56 843.24,1574.56 4724.95,1574.71 5247.36,1575.48 5299.71,1575.48 5352.06,1575.48 5404.41,1575.48 5456.76,1575.48 5509.11,1575.48 5561.46,1575.48 5613.81,1575.48 5666.16,1575.48 5718.51,1575.48 5770.86,1575.48 5823.21,1575.48 5875.56,1575.48 5927.91,1575.48 5980.26,1575.48 6032.61,1575.48 4272.63,1575.76 4817.99,1576.75 4365.67,1577.8 2908.71,1579.93 2936.21,1579.93 3669.87,1591.19 915,1600 4724.95,1601.71 4272.63,1602.76 4817.99,1603.75 4365.67,1604.8 5178.24,1605.44 2908.71,1605.85 2936.21,1605.85 3669.87,1617.12 57.72,1618.72 110.07,1618.72 162.42,1618.72 214.77,1618.72 267.12,1618.72 319.47,1618.72 371.82,1618.72 424.17,1618.72 476.52,1618.72 528.87,1618.72 581.22,1618.72 633.57,1618.72 685.92,1618.72 738.27,1618.72 790.62,1618.72 842.97,1618.72 895.32,1618.72 5247.63,1619.65 5299.98,1619.65 5352.33,1619.65 5404.68,1619.65 5457.03,1619.65 5509.38,1619.65 5561.73,1619.65 5614.08,1619.65 5666.43,1619.65 5718.78,1619.65 5771.13,1619.65 5823.48,1619.65 5875.83,1619.65 5928.18,1619.65 5980.53,1619.65 6032.88,1619.65 5197.42,1624.16 4724.95,1628.71 4272.63,1629.76 4817.99,1630.75 2908.71,1631.78 2936.21,1631.78 4365.67,1631.8 4507.87,1637.89 1402.68,1646.54 4723.99,1653.71 4271.67,1654.76 4817.03,1655.75 4364.71,1656.8 1193.68,1664.41 4723.99,1680.71 4271.67,1681.76 4817.03,1682.75 4364.71,1683.8 738.57,1691.42 4005.92,1691.63 4723.99,1707.71 4271.67,1708.76 5382.91,1709.47 4817.03,1709.75 4364.71,1710.8 577.59,1715.09 2936.21,1717.55 3330.85,1722.83 3356.05,1722.83 438.77,1740.48 1115.11,1742.86 2936.21,1743.48 2936.21,1769.4 1641.78,1785.44 2936.21,1795.33 4722.85,1808.08 4815.89,1810.12 4275.25,1813.18 4368.29,1815.22 2936.21,1821.26 3330.85,1823.05 3356.05,1823.05 278.19,1830.14 5445.14,1833.95 4722.85,1835.08 4815.89,1837.12 4275.25,1840.18 4368.29,1842.22 3330.85,1848.97 3356.05,1848.97 4722.85,1862.08 4815.89,1864.12 4275.25,1867.18 4368.29,1869.22 4721.89,1887.08 4814.93,1889.12 4274.29,1892.18 4367.33,1894.22 2908.71,1910.73 2936.21,1910.73 4721.89,1914.08 4814.93,1916.12 4651.78,1917.37 4274.29,1919.18 4367.33,1921.22 4915.83,1933.44 2908.71,1936.66 2936.21,1936.66 4721.89,1941.08 4814.93,1943.12 4274.29,1946.18 4367.33,1948.22 3669.87,1952.14 4797.89,1961.04 4741.89,1962.04 4768.89,1962.04 2908.71,1962.58 2936.21,1962.58 4350.29,1966.14 4294.29,1967.14 4321.29,1967.14 3669.87,1978.07 2712.09,1984.5 2739.59,1984.5 1376.23,1985.5 1402.37,1985.83 1428.23,1986.46 1823.94,1988.25 1850.25,1988.29 1875.94,1989.21 2908.71,1988.51 2936.21,1988.51 3669.87,2004 1353.25,2004.72 1804.03,2005.78 1446.29,2006.76 1080.3,2007.82 1897.07,2007.82 2712.09,2010.43 2739.59,2010.43 2908.71,2014.43 2936.21,2014.43 3669.87,2029.92 1353.25,2031.72 1804.03,2032.78 1446.29,2033.76 1516.92,2033.82 1897.07,2034.82 2712.09,2036.35 2739.59,2036.35 4253.29,2057.91 1353.25,2058.72 1804.03,2059.78 1446.29,2060.76 1897.07,2061.82 2712.09,2062.28 2739.59,2062.28 1352.29,2083.72 1803.07,2084.78 1445.32,2085.76 1896.11,2086.82 1167.71,2110.72 1352.29,2110.72 1803.07,2111.78 1445.32,2112.76 1896.11,2113.82 2712.09,2115.25 2739.59,2115.25 1352.29,2137.72 1803.07,2138.78 1445.32,2139.76 1896.11,2140.82 2712.09,2141.18 2739.59,2141.18 3669.26,2143.49 3785.09,2143.42 3813,2143.42 3698.14,2143.92 3726.97,2143.81 3755.91,2143.78 3841.89,2143.85 1663.13,2146.09 2712.09,2167.1 2739.59,2167.1 3669.26,2169.42 3727.02,2169.28 3698.14,2169.85 3755.91,2169.71 3841.89,2169.77 2908.71,2181.76 2936.21,2181.76 2712.09,2193.03 2739.59,2193.03 3669.26,2195.35 3727.02,2195.21 3785.09,2195.27 3813,2195.27 3698.14,2195.78 3755.91,2195.64 3841.89,2195.7 2908.71,2207.68 2936.21,2207.68 3669.26,2221.27 3727.02,2221.13 3698.14,2221.7 3755.91,2221.56 3841.89,2221.62 2908.71,2233.61 2936.21,2233.61 2398.03,2246 2712.09,2246 3669.26,2247.2 3727.02,2247.06 3755.91,2247.49 3785.09,2247.12 3813,2247.12 2770.96,2248 3698.14,2247.63 3841.89,2247.55 2908.71,2259.54 2936.21,2259.54 2712.09,2273 3669.26,2273.13 3727.02,2272.99 3755.91,2273.42 3785.09,2273.05 3813,2273.05 3698.14,2273.56 2770.96,2275 2908.71,2285.46 2936.21,2285.46 2712.09,2298 2770,2300 2712.09,2325 2770,2327 2256.92,2349.99 2281.98,2350.29 2307.47,2350.17 2361.43,2350.32 2386.42,2349.99 2411.48,2350.29 2436.47,2350.17 2712.09,2352 2770,2354 2313.67,2375.23 2355.75,2375.4 2441.85,2375.14 4696.09,2377.73 2712.09,2379 2770,2381 2256.92,2400.07 2281.98,2400.37 2307.47,2400.25 2363.28,2400.36 2388.27,2400.02 2413.33,2400.33 2438.47,2400.25 2712.09,2406 2770,2408 4393.83,2423.31 2712.09,2481 2770.96,2483 3669.26,2505.83 3698.14,2506.26 3727.02,2505.69 3755.91,2506.12 3785.09,2505.75 3813,2505.75 3841.89,2506.18 2712.09,2508 2770.96,2510 4968.03,2521.69 3669.26,2531.75 3698.14,2532.18 3727.02,2531.61 3755.91,2532.04 3841.89,2532.11 2712.09,2533 2908.75,2533.08 2936.25,2533.08 2770,2535 3669.26,2557.68 3698.14,2558.11 3727.02,2557.54 3755.91,2557.97 3785.09,2557.6 3813,2557.6 3841.89,2558.03 2908.75,2559.01 2936.25,2559.01 2712.09,2560 2770,2562 4034.45,2571.88 3727.02,2583.47 3669.26,2583.61 3698.14,2584.04 3755.91,2583.9 3841.89,2583.96 2908.75,2584.93 2936.25,2584.93 2712.09,2587 2770,2589 3727.02,2609.39 3785.09,2609.45 3813,2609.45 3669.26,2609.53 3698.14,2609.96 3755.91,2609.82 3841.89,2609.88 2908.75,2610.86 2936.25,2610.86 2712.09,2614 2770,2616 3669.26,2635.46 3727.02,2635.32 3785.09,2635.38 3813,2635.38 3698.14,2635.89 3755.91,2635.75 2908.75,2636.79 2936.25,2636.79 2712.09,2641 2770,2643 4294.29,2690.63 4321.29,2690.63 4744.29,2690.63 4771.29,2690.63 4350.29,2691.63 4800.29,2691.63 4367.33,2709.55 4817.33,2709.55 4274.29,2711.59 4724.29,2711.59 3669.26,2717.2 5493.95,2734.53 4367.33,2736.55 4817.33,2736.55 4274.29,2738.59 4724.29,2738.59 3669.26,2743.13 1507.19,2751.99 4367.33,2763.55 4817.33,2763.55 4274.29,2765.59 4724.29,2765.59 3669.26,2769.05 1188.88,2778.15 4368.29,2788.55 4818.29,2788.55 5962.54,2788.66 4275.25,2790.59 4725.25,2790.59 3669.26,2794.98 4368.29,2815.55 4818.29,2815.55 4275.25,2817.59 4725.25,2817.59 4368.29,2842.55 4818.29,2842.55 4275.25,2844.59 4725.25,2844.59 5153.72,2850.52 5653.82,2864.17 4928.55,2878.36 1765.21,2895.14 3774.57,2921.22 3801.57,2921.22 3828.57,2921.22 3854.29,2924.9 3746.41,2927.71 5486.22,2937.13 4056.32,2940.22 4719.77,2952.59 3852.82,2954.17 3746.64,2955.57 3352.05,2960.32 3773.12,2962.58 3800.12,2962.58 3827.12,2962.58 4436.76,3040.74 3755.68,3056.21 5241.87,3070.13 5965.64,3094.87 4195.51,3099.51 4920.82,3105.69 1996.9,3129.47 3851.57,3158.28 3568.56,3217.04 5828,3221.68 4333.66,3225 4748.54,3240.24 5309.92,3271.17 4119.11,3274.27 4333.66,3357.75 2062.2,3372.14 2318.64,3394.24 4037.15,3408.81 3676.81,3416.54 5981.1,3418.09 3300,3419.95 1979.51,3440.02 2760.85,3443.08 3082.73,3467.4 4981.3,3474.54 2296.08,3476.77 4530.44,3487.46 2556.52,3490.45 5630.61,3534.93 5208.68,3562.99 2940.68,3566.56 3956.69,3570.72 5866.66,3605.22 5493.95,3724.03 4094.49,3789.37 5162.69,3792.34 4911.42,3801.75 3498.52,3806.26 3749.5,3806.26 2159.69,3821.73 4678.95,3834.1 2803.04,3837.19 3188.12,3865.03 4501.1,3865.03 5630.05,3875.86 5257.34,4007.31 5517.15,4011.95 1820.87,4040.25 2315.85,4040.25 2844.49,4040.57 3495.1,4045.28 4014.72,4045.28 4489.08,4045.28
  other v2: 105,1050 145,1050 185,1050 225,1050 711.27,1050 751.27,1050 791.27,1050 5308.73,1050 5348.73,1050 5388.73,1050 5875,1050 5915,1050 5955,1050 5995,1050 105,1090 145,1090 185,1090 225,1090 791.27,1090 5308.73,1090 5875,1090 5915,1090 5955,1090 5995,1090 105,1130 145,1130 185,1130 225,1130 791.27,1130 5308.73,1130 5875,1130 5915,1130 5955,1130 5995,1130 105,1170 145,1170 185,1170 225,1170 5875,1170 5915,1170 5955,1170 5995,1170 105,1210 145,1210 185,1210 225,1210 5875,1210 5915,1210 5955,1210 5995,1210 105,1250 145,1250 185,1250 225,1250 5875,1250 5915,1250 5955,1250 5995,1250 105,1300 145,1300 185,1300 225,1300 5875,1300 5915,1300 5955,1300 5995,1300 105,1340 145,1340 185,1340 225,1340 5875,1340 5915,1340 5955,1340 5995,1340 105,1380 145,1380 185,1380 225,1380 5875,1380 5915,1380 5955,1380 5995,1380 105,1420 145,1420 185,1420 225,1420 791.27,1420 5308.73,1420 5875,1420 5915,1420 5955,1420 5995,1420 105,1460 145,1460 185,1460 225,1460 791.27,1460 5308.73,1460 5875,1460 5915,1460 5955,1460 5995,1460 105,1500 145,1500 185,1500 225,1500 711.27,1500 751.27,1500 791.27,1500 5308.73,1500 5348.73,1500 5388.73,1500 5875,1500 5915,1500 5955,1500 5995,1500
HB1: C13.2 U1.9 | length 149.8
  Top Layer w13.5: U1.9@2644.58,1704.29 U1.9@2659.31,1704.29 ; U1.9@2662.78,1704.17 2745.72,1621.23 2745.72,1615.57 2748.97,1612.32 C13.2@2756.47,1612.32
HB2: C14.1 U1.16 | length 148.8
  Top Layer w13.5: U1.16@2645.01,1845.97 2661.93,1845.97 C14.1@2755.16,1939.2
HO1: R21.2 R25.2 U1.8 | length 1460.9
  Top Layer w10: U1.8@2627.9,1680.51 2627.9,1678.73 2627.98,1678.65 2635.88,1678.65 v1(2637.74,1676.79)
  Top Layer w14: U1.8@2627.96,1674.37 U1.8@2627.96,1686.37
  Top Layer w20: R21.2@3251.27,1225.42 v1(3274.75,1225.42) ; R25.2@3268.23,855.82 3274.75,862.34 v1(3274.75,875.09)
  Signal Layer 4 w24: v1(2637.74,1676.79) 2667.95,1676.79 2752.14,1592.6 2874.11,1470.63 2874.11,1319.5 3005.19,1188.42 3210.94,1188.42 3225,1174.36 3225,1064.22 3239.06,1050.16 3250.82,1050.16 ; v1(3274.75,875.09) 3274.75,1032.21 3256.65,1050.31 3274.75,1068.41 v1(3274.75,1225.42)
HO2: R23.1 R27.1 U1.17 | length 1501.9
  Top Layer w10: U1.17@2627.84,1869.54 2627.84,1871.69 U1.17@2627.92,1871.77
  Top Layer w14: U1.17@2627.9,1863.49 U1.17@2627.9,1875.49
  Top Layer w20: R23.1@3249.01,2076.54 v1(3272.49,2076.54) ; R27.1@3249.03,2425.38 3249.03,2424.5 3271.3,2424.5 v1(3272.06,2423.74)
  Signal Layer 4 w24: v1(2637.55,1871.77) 2669.37,1871.77 2799.2,2001.6 2870,2072.4 2870,2301.79 2957.06,2388.85 3201.15,2388.85 3225,2365 3225,2266.17 3239.06,2252.11 3250,2252.11 ; v1(3272.49,2076.54) 3272.49,2235.6 3255.82,2252.26 3273.43,2269.87 v1@3273.43,2426.69
ILIM/IMON: J9.19 J10.19 R7.2 R8.2 U1.31 | length 3638.5
  Top Layer w10: R7.2@2308.21,1765.47 R8.2@2308.21,1723.87 2315.71,1723.87 2320.71,1718.87 2320.71,1714.91 2326.56,1709.06 v1(2403.48,1709.06) ; v1@2401.25,1706.82 2406.16,1711.73 2428.42,1711.73 2442.39,1725.71 U1.31@2457.7,1725.71
  Signal Layer 4 w10: J10.19@750,3570 750,3674.65 799.93,3724.57 799.93,3803.27 766.02,3837.18 766.02,3837.42 750,3853.44 J9.19@750,3868.31 ; v1(1641.78,3267.72) 1774.47,3267.72 1816.24,3225.95 1816.24,2930.84 1991.29,2755.79 1991.29,2260.18 2057.15,2194.32 2057.15,2108.12 2293.85,1871.42 2293.85,1747.89 2345.45,1696.29 2389.83,1696.29 2402.59,1709.06 v1(2403.48,1709.06)
  Bottom Layer w10: J10.19@750,3570 750,3556.9 801.58,3505.32 801.58,3401.8 896.29,3307.09 1274.33,3307.09 1313.7,3267.72 v1(1641.78,3267.72)
L1: L1.2 R11.1 R12.1 | length 596.9
  Bottom Layer w10: v4(2302,410) 2314.99,397.01 2382.58,397.01 2382.57,397.25
  Bottom Layer w40: 2382.57,397.25 cw(c2302,410) 2382.85,399.1
L2: L2.1 R13.2 R14.2 | length 596
  Bottom Layer w10: v4(2302,3120) 2312.9,3109.1 2382.85,3109.1
  Bottom Layer w40: 2382.57,3107.25 cw(c2302,3120) 2382.85,3109.1
LO1: R22.1 R26.1 U1.11 | length 1829.2
  Top Layer w10: R26.1@2920.72,875.09 R26.1@2925.19,870.62 ; R22.1@2920.75,1225.42 R22.1@2925.22,1220.95
  Top Layer w13.5: U1.11@2645.62,1743.48 2653.49,1743.48 2690.03,1743.48 v1(2726.75,1706.75)
  Top Layer w22: v1(2907.29,1225.42) R22.1@2920.75,1225.42 ; v1@2907.64,874.71 v1(2907.25,875.09) R26.1@2920.72,875.09
  Signal Layer 1 w24: v1(2726.75,1706.75) 2805,1706.75 2855.95,1706.75 2875,1687.7 2875,1452.91 2810,1387.91 2810,1070 ; 2810,1070 2828.62,1051.38 ; 2810,1070 2828.62,1051.38 ; 2828.62,1051.38 2851.77,1051.38 ; 2828.62,1051.38 2851.77,1051.38 ; 2851.77,1051.38 2875.25,1074.86 ; 2851.77,1051.38 2875.25,1074.86 ; 2851.77,1051.38 2875.25,1027.89 ; 2851.77,1051.38 2875.25,1027.89 ; 2875.25,907.1 2875.25,1027.89 ; 2875.25,907.1 2875.25,1027.89 ; 2875.25,907.1 v1(2907.25,875.09) 2875.25,907.1 ; 2875.25,1074.86 2875.25,1194.03 ; 2875.25,1074.86 2875.25,1194.03 ; 2875.25,1194.03 2906.96,1225.74 2875.25,1194.03
LO2: R24.2 R28.2 U1.14 | length 1487.2
  Top Layer w10: R28.2@2920.47,2426.28 R28.2@2924.94,2421.81 ; R24.2@2920.72,2075.09 R24.2@2925.19,2070.62
  Top Layer w13.5: U1.14@2645.62,1806.52 2653.49,1806.52 2688.5,1806.52 2725.44,1843.46 v1(2727,1843.46)
  Top Layer w22: v1(2907,2426.28) R28.2@2920.47,2426.28 ; v1(2907.25,2075.09) R24.2@2920.72,2075.09
  Signal Layer 1 w24: v1(2727,1843.46) 2773.3,1843.46 2805,1875.16 2805,2235 ; 2805,2235 2820,2250 ; 2805,2235 2820,2250 ; 2820,2250 2851.52,2250 ; 2820,2250 2851.52,2250 ; 2851.52,2250 2875,2226.52 ; 2851.52,2250 2875,2226.52 ; 2851.52,2250 2875,2273.48 ; 2851.52,2250 2875,2273.48 ; 2875,2107.34 2875,2226.52 ; 2875,2107.34 v1(2907.25,2075.09) 2875,2107.34 ; 2875,2107.34 2875,2226.52 ; 2875,2273.48 2875,2394.28 ; 2875,2273.48 2875,2394.28 ; 2875,2394.28 v1(2907,2426.28) 2875,2394.28
MODE: J10.17 JP3.2 R100.1 U1.29 | length 3936.9
  Top Layer w10: R100.1@800.71,3994.89 800.71,3725.93 850,3676.65 J10.17@850,3570 ; R100.1@800.71,4004.73 R100.1@800.71,4015.75 ; v1@2412.11,1759.38 v1@2417.88,1765.16 ; v1(2413.7,1763.61) 2415.25,1765.16 U1.29@2464.51,1765.16
  Top Layer w24: R100.1@801.1,4004.9 v1(801.1,4026.69)
  Signal Layer 2 w10: v1(1716.17,3363.9) 1727.21,3352.86 1783.18,3352.86 1854.46,3281.59 1854.46,2901.74 1983.49,2772.71 1983.49,2303.35 2075.5,2211.34 2075.5,2131.11 2342.81,1863.8 2342.81,1814.72 2393.58,1763.95 2413.36,1763.95 v1(2413.7,1763.61)
  Signal Layer 3 w10: JP3.2@1050,3000 1064.87,3000 1079.05,3014.17 1082.97,3014.17 1134.44,3065.64 1134.44,3397.41 v1(1134.64,3397.61)
  Bottom Layer w10: J10.17@850,3570 900.17,3519.83 900.17,3438.94 942.88,3396.22 1133.25,3396.22 v1(1134.64,3397.61) 1366.11,3397.61 1367.49,3396.22 1683.85,3396.22 v1(1716.17,3363.9)
  Bottom Layer w24: v1@801.1,4004.9 v1(801.1,4026.69)
  other v1: 800.93,4004.73
MODE_SEC: J9.17 R100.2 | length 199.6
  Top Layer w10: J9.17@850,3868.31 844.06,3874.25 844.06,3993.19 855.6,4004.73 v1(860.93,4004.73) ; R100.2@856.01,4015.75 858.36,4013.39 R100.2@861.01,4010.75
  Top Layer w24: R100.2@861.1,4004.9 v1(861.1,4026.69)
  Bottom Layer w24: v1@861.1,4004.9 v1(861.1,4026.69)
NetC5_1: C5.1 C6.1 R95.2 U1.3 | length 313
  Top Layer w10: R95.2@2376.42,1472.08 2377.05,1472.71 2432.26,1472.71 2432.89,1473.34 2440.39,1473.34 2462.68,1495.63 2462.68,1529.47 2480.56,1547.35 2480.56,1569.14 2485.56,1574.14 C6.1@2493.06,1574.14 2493.06,1605.33 2529.47,1641.75 U1.3@2529.47,1680.51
